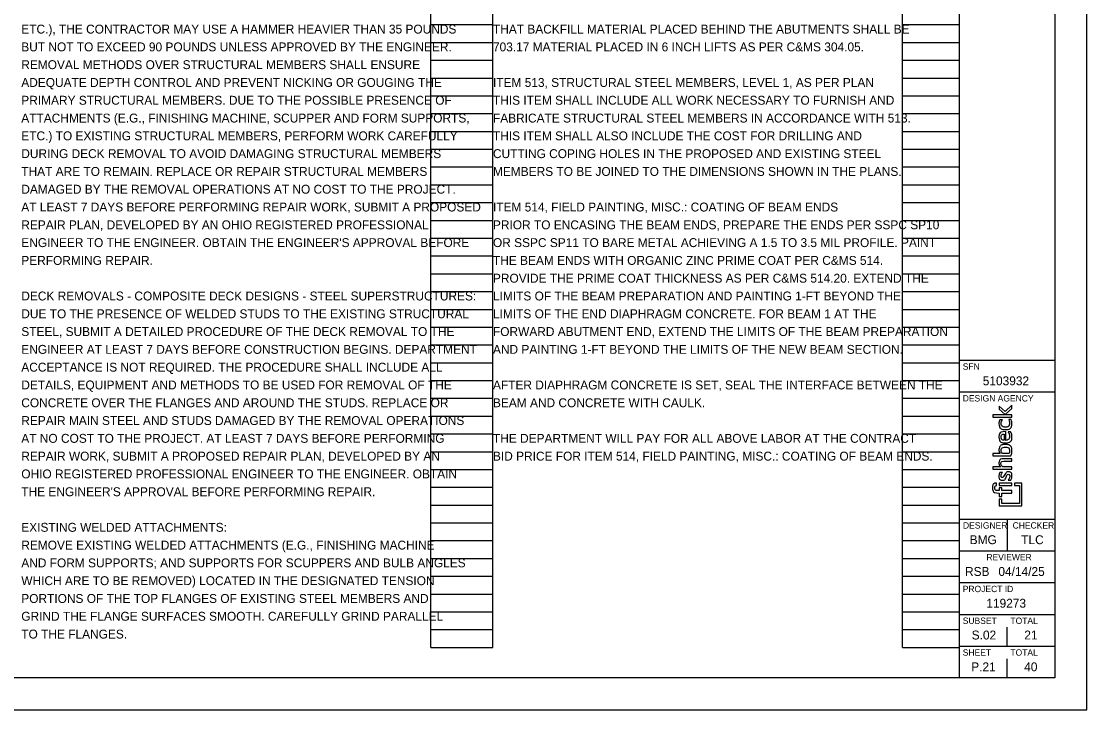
# Model space of a CAD drawing. Extents: x 0 to 34, y 0 to 22.
# Drawn here: x 17.24 to 34, y 0 to 10.83 of the extents above; entities that cross this region are included whole.
import ezdxf

# ---------------------------------------------------------------- set-up
doc = ezdxf.new("R2010")
doc.units = 0
for name, color, linetype in [('SH_Border', 7, 'Continuous'), ('SH_Cut_Line', 7, 'Continuous'), ('SH_Data', 7, 'Continuous'), ('SH_Text', 7, 'Continuous')]:
    doc.layers.add(name, color=color, linetype=linetype)

msp = doc.modelspace()

# ---------------------------------------------------------------- linework, layer by layer
at = {"layer": 'SH_Border'}
for p, q in [((32, 0.5), (32, 21.5)), ((32, 5.5), (33.5, 5.5)), ((32, 5), (33.5, 5)), ((32, 3), (33.5, 3)), ((32.75, 3), (32.75, 2.5)), ((32, 2.5), (33.5, 2.5)), ((32, 2), (33.5, 2)), ((32, 1.5), (33.5, 1.5)), ((32, 1), (33.5, 1))]:
    msp.add_line(p, q, dxfattribs=at)
msp.add_lwpolyline([(1.5, 21.5), (33.5, 21.5), (33.5, 0.5), (1.5, 0.5)], close=True, dxfattribs=at)
at = {"layer": 'SH_Cut_Line'}
msp.add_lwpolyline([(0, 0), (34, 0), (34, 22), (0, 22)], close=True, dxfattribs=at)
at = {"layer": 'SH_Data'}
for p, q in [((23.68, 0.98), (23.68, 21.14)), ((24.66, 0.98), (24.66, 21.14)), ((31.1, 0.98), (31.1, 21.14)), ((32, 0.98), (32, 21.14)), ((23.68, 10.78), (24.66, 10.78)), ((31.1, 10.78), (32, 10.78)), ((23.68, 10.5), (24.66, 10.5)), ((31.1, 10.5), (32, 10.5)), ((23.68, 10.22), (24.66, 10.22)), ((31.1, 10.22), (32, 10.22)), ((23.68, 9.94), (24.66, 9.94)), ((31.1, 9.94), (32, 9.94)), ((23.68, 9.66), (24.66, 9.66)), ((31.1, 9.66), (32, 9.66)), ((23.68, 9.38), (24.66, 9.38)), ((31.1, 9.38), (32, 9.38)), ((23.68, 9.1), (24.66, 9.1)), ((31.1, 9.1), (32, 9.1)), ((23.68, 8.82), (24.66, 8.82)), ((31.1, 8.82), (32, 8.82)), ((23.68, 8.54), (24.66, 8.54)), ((31.1, 8.54), (32, 8.54)), ((23.68, 8.26), (24.66, 8.26)), ((31.1, 8.26), (32, 8.26)), ((23.68, 7.98), (24.66, 7.98)), ((31.1, 7.98), (32, 7.98)), ((23.68, 7.7), (24.66, 7.7)), ((31.1, 7.7), (32, 7.7)), ((23.68, 7.42), (24.66, 7.42)), ((31.1, 7.42), (32, 7.42)), ((23.68, 7.14), (24.66, 7.14)), ((31.1, 7.14), (32, 7.14)), ((23.68, 6.86), (24.66, 6.86)), ((31.1, 6.86), (32, 6.86)), ((23.68, 6.58), (24.66, 6.58)), ((31.1, 6.58), (32, 6.58)), ((23.68, 6.3), (24.66, 6.3)), ((31.1, 6.3), (32, 6.3)), ((23.68, 6.02), (24.66, 6.02)), ((31.1, 6.02), (32, 6.02)), ((23.68, 5.74), (24.66, 5.74)), ((31.1, 5.74), (32, 5.74)), ((23.68, 5.46), (24.66, 5.46)), ((31.1, 5.46), (32, 5.46)), ((23.68, 5.18), (24.66, 5.18)), ((31.1, 5.18), (32, 5.18)), ((23.68, 4.9), (24.66, 4.9)), ((31.1, 4.9), (32, 4.9)), ((32.623, 4.777), (32.623, 4.73)), ((32.72, 4.693), (32.623, 4.777)), ((32.623, 4.73), (32.72, 4.643)), ((32.82, 4.794), (32.72, 4.693)), ((32.72, 4.643), (32.82, 4.742)), ((32.82, 4.742), (32.82, 4.794)), ((23.68, 4.62), (24.66, 4.62)), ((31.1, 4.62), (32, 4.62)), ((32.522, 4.642), (32.522, 4.603)), ((32.82, 4.642), (32.522, 4.642)), ((32.522, 4.603), (32.82, 4.603)), ((32.675, 4.562), (32.633, 4.562)), ((32.812, 4.566), (32.774, 4.566)), ((32.82, 4.603), (32.82, 4.642)), ((32.727, 4.238), (32.727, 4.376)), ((32.8, 4.372), (32.763, 4.372)), ((23.68, 4.34), (24.66, 4.34)), ((31.1, 4.34), (32, 4.34)), ((32.702, 4.337), (32.702, 4.239)), ((23.68, 4.06), (24.66, 4.06)), ((31.1, 4.06), (32, 4.06)), ((32.781, 4.033), (32.675, 4.033)), ((32.75, 4), (32.75, 4)), ((23.68, 3.78), (24.66, 3.78)), ((31.1, 3.78), (32, 3.78)), ((32.674, 3.735), (32.636, 3.735)), ((32.58, 3.527), (32.58, 3.566)), ((32.623, 3.566), (32.623, 3.527)), ((32.82, 3.566), (32.623, 3.566)), ((32.623, 3.527), (32.82, 3.527)), ((32.764, 3.611), (32.806, 3.611)), ((32.82, 3.527), (32.82, 3.566)), ((32.982, 3.566), (32.863, 3.566)), ((32.863, 3.566), (32.863, 3.527)), ((32.863, 3.527), (32.943, 3.527)), ((32.943, 3.527), (32.943, 3.246)), ((32.982, 3.207), (32.982, 3.566)), ((23.68, 3.5), (24.66, 3.5)), ((31.1, 3.5), (32, 3.5)), ((23.68, 3.22), (24.66, 3.22)), ((31.1, 3.22), (32, 3.22)), ((32.663, 3.313), (32.624, 3.313)), ((32.624, 3.313), (32.624, 3.207)), ((32.624, 3.207), (32.982, 3.207)), ((32.663, 3.246), (32.663, 3.313)), ((32.943, 3.246), (32.663, 3.246)), ((23.68, 2.94), (24.66, 2.94)), ((31.1, 2.94), (32, 2.94)), ((23.68, 2.66), (24.66, 2.66)), ((31.1, 2.66), (32, 2.66)), ((23.68, 2.38), (24.66, 2.38)), ((31.1, 2.38), (32, 2.38)), ((23.68, 2.1), (24.66, 2.1)), ((31.1, 2.1), (32, 2.1)), ((23.68, 1.82), (24.66, 1.82)), ((31.1, 1.82), (32, 1.82)), ((23.68, 1.54), (24.66, 1.54)), ((31.1, 1.54), (32, 1.54)), ((23.68, 1.26), (24.66, 1.26)), ((31.1, 1.26), (32, 1.26)), ((32.75, 1), (32.75, 1.3)), ((23.68, 0.98), (24.66, 0.98)), ((31.1, 0.98), (32, 0.98)), ((32.375, 0.675), (32.375, 0.675)), ((32.75, 0.5), (32.75, 0.8))]:
    msp.add_line(p, q, dxfattribs=at)
for points in [[(32.637, 4.033), (32.522, 4.033), (32.522, 3.994), (32.809, 3.994)], [(32.698, 3.911), (32.82, 3.911), (32.82, 3.949), (32.699, 3.949)], [(32.649, 3.824), (32.649, 3.823), (32.522, 3.823), (32.522, 3.784), (32.82, 3.784), (32.82, 3.823), (32.679, 3.823)], [(32.623, 3.409), (32.623, 3.357), (32.663, 3.357), (32.663, 3.409), (32.82, 3.409), (32.82, 3.448), (32.663, 3.448), (32.663, 3.492), (32.623, 3.492), (32.623, 3.448)]]:
    msp.add_lwpolyline(points, dxfattribs=at)
for points in [[(32.633, 4.562), (32.625, 4.543), (32.62, 4.528), (32.62, 4.505), (32.62, 4.446), (32.661, 4.408), (32.725, 4.408), (32.783, 4.408), (32.824, 4.449), (32.824, 4.508), (32.824, 4.528), (32.818, 4.553), (32.812, 4.566)], [(32.774, 4.566), (32.782, 4.547), (32.787, 4.531), (32.787, 4.514), (32.787, 4.474), (32.762, 4.448), (32.722, 4.448), (32.682, 4.448), (32.655, 4.472), (32.655, 4.508), (32.655, 4.525), (32.66, 4.54), (32.675, 4.562)], [(32.727, 4.376), (32.655, 4.376), (32.62, 4.343), (32.62, 4.291), (32.62, 4.236), (32.66, 4.199), (32.719, 4.199), (32.773, 4.199), (32.824, 4.233), (32.824, 4.294), (32.824, 4.327), (32.816, 4.349), (32.8, 4.372)], [(32.763, 4.372), (32.778, 4.35), (32.786, 4.327), (32.786, 4.304), (32.786, 4.266), (32.766, 4.244), (32.727, 4.238)], [(32.702, 4.239), (32.671, 4.244), (32.653, 4.262), (32.653, 4.291), (32.653, 4.319), (32.672, 4.336), (32.702, 4.337)], [(32.809, 3.994), (32.818, 4.013), (32.824, 4.041), (32.824, 4.067), (32.824, 4.133), (32.784, 4.172), (32.717, 4.172), (32.661, 4.172), (32.62, 4.136), (32.62, 4.087), (32.62, 4.068), (32.625, 4.05), (32.637, 4.033)], [(32.675, 4.033), (32.66, 4.05), (32.654, 4.061), (32.654, 4.078), (32.654, 4.11), (32.682, 4.132), (32.723, 4.132), (32.76, 4.132), (32.787, 4.107), (32.787, 4.072), (32.787, 4.061), (32.784, 4.044), (32.781, 4.033)], [(32.699, 3.949), (32.646, 3.949), (32.62, 3.921), (32.62, 3.883), (32.62, 3.861), (32.63, 3.839), (32.649, 3.824)], [(32.679, 3.823), (32.658, 3.842), (32.651, 3.855), (32.651, 3.872), (32.651, 3.896), (32.669, 3.911), (32.698, 3.911)], [(32.636, 3.735), (32.625, 3.714), (32.62, 3.695), (32.62, 3.677), (32.62, 3.638), (32.64, 3.612), (32.673, 3.612), (32.726, 3.612), (32.74, 3.704), (32.767, 3.704), (32.781, 3.704), (32.789, 3.691), (32.789, 3.675), (32.789, 3.659), (32.781, 3.636), (32.764, 3.611)], [(32.806, 3.611), (32.819, 3.636), (32.824, 3.655), (32.824, 3.679), (32.824, 3.716), (32.8, 3.744), (32.766, 3.744), (32.746, 3.744), (32.732, 3.732), (32.711, 3.7), (32.691, 3.665), (32.68, 3.652), (32.672, 3.652), (32.661, 3.652), (32.654, 3.662), (32.654, 3.678), (32.654, 3.692), (32.66, 3.713), (32.674, 3.735)], [(32.58, 3.566), (32.542, 3.565), (32.518, 3.536), (32.518, 3.492), (32.518, 3.439), (32.551, 3.408), (32.623, 3.409)], [(32.623, 3.448), (32.576, 3.445), (32.553, 3.461), (32.553, 3.492), (32.553, 3.509), (32.561, 3.52), (32.58, 3.527)]]:
    msp.add_open_spline(points, degree=3, dxfattribs=at)

# ---------------------------------------------------------------- texts
for s, height, p in [('SFN', 0.1, (32.05, 5.35)), ('5103932', 0.14, (32.365, 5.105)), ('DESIGN AGENCY', 0.1, (32.05, 4.85)), ('DESIGNER', 0.1, (32.054, 2.85)), ('CHECKER', 0.1, (32.835, 2.85)), ('BMG', 0.14, (32.159, 2.605)), ('TLC', 0.14, (32.97, 2.605)), ('REVIEWER', 0.1, (32.422, 2.35)), ('RSB', 0.14, (32.086, 2.105)), ('04/14/25', 0.14, (32.611, 2.105)), ('PROJECT ID', 0.1, (32.05, 1.85)), ('119273', 0.14, (32.421, 1.605)), ('SUBSET', 0.1, (32.05, 1.35)), ('TOTAL', 0.1, (32.8, 1.35)), ('S.02', 0.14, (32.191, 1.105)), ('21', 0.14, (33.019, 1.105)), ('SHEET', 0.1, (32.05, 0.85)), ('TOTAL', 0.1, (32.8, 0.85)), ('P.21', 0.14, (32.184, 0.605)), ('40', 0.14, (33.017, 0.605))]:
    msp.add_text(s, height=height, dxfattribs=at).set_placement(p)
at = {"layer": 'SH_Text'}
for s, p in [('ETC.), THE CONTRACTOR MAY USE A HAMMER HEAVIER THAN 35 POUNDS ', (17.24, 10.64)), ('THAT BACKFILL MATERIAL PLACED BEHIND THE ABUTMENTS SHALL BE', (24.66, 10.64)), ('BUT NOT TO EXCEED 90 POUNDS UNLESS APPROVED BY THE ENGINEER. ', (17.24, 10.36)), ('703.17 MATERIAL PLACED IN 6 INCH LIFTS AS PER C&MS 304.05.', (24.66, 10.36)), ('REMOVAL METHODS OVER STRUCTURAL MEMBERS SHALL ENSURE ', (17.24, 10.08)), ('ADEQUATE DEPTH CONTROL AND PREVENT NICKING OR GOUGING THE ', (17.24, 9.8)), ('ITEM 513, STRUCTURAL STEEL MEMBERS, LEVEL 1, AS PER PLAN', (24.66, 9.8)), ('PRIMARY STRUCTURAL MEMBERS. DUE TO THE POSSIBLE PRESENCE OF', (17.24, 9.52)), ('THIS ITEM SHALL INCLUDE ALL WORK NECESSARY TO FURNISH AND', (24.66, 9.52)), ('ATTACHMENTS (E.G., FINISHING MACHINE, SCUPPER AND FORM SUPPORTS, ', (17.24, 9.24)), ('FABRICATE STRUCTURAL STEEL MEMBERS IN ACCORDANCE WITH 513.', (24.66, 9.24)), ('ETC.) TO EXISTING STRUCTURAL MEMBERS, PERFORM WORK CAREFULLY ', (17.24, 8.96)), ('THIS ITEM SHALL ALSO INCLUDE THE COST FOR DRILLING AND ', (24.66, 8.96)), ('DURING DECK REMOVAL TO AVOID DAMAGING STRUCTURAL MEMBERS ', (17.24, 8.68)), ('CUTTING COPING HOLES IN THE PROPOSED AND EXISTING STEEL ', (24.66, 8.68)), ('THAT ARE TO REMAIN. REPLACE OR REPAIR STRUCTURAL MEMBERS ', (17.24, 8.4)), ('MEMBERS TO BE JOINED TO THE DIMENSIONS SHOWN IN THE PLANS.', (24.66, 8.4)), ('DAMAGED BY THE REMOVAL OPERATIONS AT NO COST TO THE PROJECT. ', (17.24, 8.12)), ('AT LEAST 7 DAYS BEFORE PERFORMING REPAIR WORK, SUBMIT A PROPOSED ', (17.24, 7.84)), ('ITEM 514, FIELD PAINTING, MISC.: COATING OF BEAM ENDS', (24.66, 7.84)), ('REPAIR PLAN, DEVELOPED BY AN OHIO REGISTERED PROFESSIONAL ', (17.24, 7.56)), ('PRIOR TO ENCASING THE BEAM ENDS, PREPARE THE ENDS PER SSPC SP10', (24.66, 7.56)), ("ENGINEER TO THE ENGINEER. OBTAIN THE ENGINEER'S APPROVAL BEFORE ", (17.24, 7.28)), ('OR SSPC SP11 TO BARE METAL ACHIEVING A 1.5 TO 3.5 MIL PROFILE. PAINT', (24.66, 7.28)), ('PERFORMING REPAIR.', (17.24, 7)), ('THE BEAM ENDS WITH ORGANIC ZINC PRIME COAT PER C&MS 514. ', (24.66, 7)), ('PROVIDE THE PRIME COAT THICKNESS AS PER C&MS 514.20. EXTEND THE ', (24.66, 6.72)), ('DECK REMOVALS - COMPOSITE DECK DESIGNS - STEEL SUPERSTRUCTURES: ', (17.24, 6.44)), ('LIMITS OF THE BEAM PREPARATION AND PAINTING 1-FT BEYOND THE ', (24.66, 6.44)), ('DUE TO THE PRESENCE OF WELDED STUDS TO THE EXISTING STRUCTURAL ', (17.24, 6.16)), ('LIMITS OF THE END DIAPHRAGM CONCRETE. FOR BEAM 1 AT THE ', (24.66, 6.16)), ('STEEL, SUBMIT A DETAILED PROCEDURE OF THE DECK REMOVAL TO THE ', (17.24, 5.88)), ('FORWARD ABUTMENT END, EXTEND THE LIMITS OF THE BEAM PREPARATION ', (24.66, 5.88)), ('ENGINEER AT LEAST 7 DAYS BEFORE CONSTRUCTION BEGINS. DEPARTMENT ', (17.24, 5.6)), ('AND PAINTING 1-FT BEYOND THE LIMITS OF THE NEW BEAM SECTION. ', (24.66, 5.6)), ('ACCEPTANCE IS NOT REQUIRED. THE PROCEDURE SHALL INCLUDE ALL ', (17.24, 5.32)), ('DETAILS, EQUIPMENT AND METHODS TO BE USED FOR REMOVAL OF THE ', (17.24, 5.04)), ('AFTER DIAPHRAGM CONCRETE IS SET, SEAL THE INTERFACE BETWEEN THE', (24.66, 5.04)), ('CONCRETE OVER THE FLANGES AND AROUND THE STUDS. REPLACE OR ', (17.24, 4.76)), ('BEAM AND CONCRETE WITH CAULK.', (24.66, 4.76)), ('REPAIR MAIN STEEL AND STUDS DAMAGED BY THE REMOVAL OPERATIONS', (17.24, 4.48)), ('AT NO COST TO THE PROJECT. AT LEAST 7 DAYS BEFORE PERFORMING', (17.24, 4.2)), ('THE DEPARTMENT WILL PAY FOR ALL ABOVE LABOR AT THE CONTRACT', (24.66, 4.2)), ('REPAIR WORK, SUBMIT A PROPOSED REPAIR PLAN, DEVELOPED BY AN', (17.24, 3.92)), ('BID PRICE FOR ITEM 514, FIELD PAINTING, MISC.: COATING OF BEAM ENDS.', (24.66, 3.92)), ('OHIO REGISTERED PROFESSIONAL ENGINEER TO THE ENGINEER. OBTAIN ', (17.24, 3.64)), ("THE ENGINEER'S APPROVAL BEFORE PERFORMING REPAIR.", (17.24, 3.36)), ('EXISTING WELDED ATTACHMENTS: ', (17.24, 2.8)), ('REMOVE EXISTING WELDED ATTACHMENTS (E.G., FINISHING MACHINE ', (17.24, 2.52)), ('AND FORM SUPPORTS; AND SUPPORTS FOR SCUPPERS AND BULB ANGLES ', (17.24, 2.24)), ('WHICH ARE TO BE REMOVED) LOCATED IN THE DESIGNATED TENSION ', (17.24, 1.96)), ('PORTIONS OF THE TOP FLANGES OF EXISTING STEEL MEMBERS AND ', (17.24, 1.68)), ('GRIND THE FLANGE SURFACES SMOOTH. CAREFULLY GRIND PARALLEL ', (17.24, 1.4)), ('TO THE FLANGES.', (17.24, 1.12))]:
    msp.add_text(s, height=0.14, dxfattribs=at).set_placement(p)

doc.saveas('drawing.dxf')
